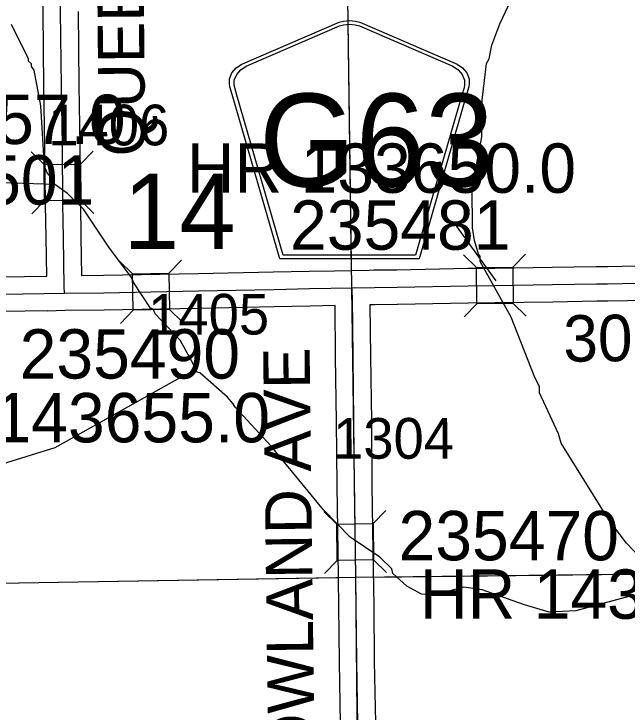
# Model space of a CAD drawing. Extents: x 23.6 to 68.7, y -63 to -29.
# Drawn here: x 49.171 to 50.226, y -54.804 to -53.602 of the extents above; entities that cross this region are included whole.
import ezdxf

# ---------------------------------------------------------------- set-up
doc = ezdxf.new("R2010")
doc.units = 0
for name, color, linetype in [('tdCoHydroRiver', 7, 'Continuous'), ('tdCoSecRdNmbr', 7, 'Continuous'), ('tdCoSecRdTxt', 7, 'Continuous'), ('tdCoSecRteBand', 7, 'Continuous'), ('tdCoSecRteCL', 7, 'Continuous'), ('tdCoSectLine', 7, 'Continuous'), ('tdCoSectLinePart', 7, 'Continuous'), ('tdCoSectNmbr', 7, 'Continuous'), ('tdCoShieldCoRte', 7, 'Continuous'), ('tdCoStrucSec', 7, 'Continuous'), ('tdCoStrucSecCoName', 7, 'Continuous'), ('tdCoStrucSecFHWANum', 7, 'Continuous'), ('tdCoSurfGravel', 7, 'Continuous')]:
    doc.layers.add(name, color=color, linetype=linetype)

msp = doc.modelspace()

# ---------------------------------------------------------------- linework, layer by layer
at = {"layer": 'tdCoHydroRiver'}
for points in [[(50.3308, -54.624), (50.3291, -54.6114), (50.2494, -54.5381), (50.2254, -54.5131), (50.195, -54.4724), (50.1131, -54.3407), (50.1082, -54.3249), (50.0758, -54.2543), (50.0757, -54.2432), (50.0676, -54.2275), (50.027, -54.1238), (49.9739, -54.0281), (49.9738, -54.0186), (49.9706, -54.0155), (49.964, -53.9919), (49.9606, -53.9698), (49.9599, -53.9019), (49.9763, -53.8133), (49.9772, -53.7502), (49.9843, -53.687), (49.989, -53.679), (49.9935, -53.6553), (50.0073, -53.6188), (50.052, -53.5236)], [(49.2416, -53.8956), (49.2367, -53.8846), (49.2287, -53.8752), (49.2238, -53.8642), (49.218, -53.7601), (49.2062, -53.6987), (49.2014, -53.6924), (49.2014, -53.6877), (49.1966, -53.683), (49.1965, -53.6782), (49.1788, -53.6437), (49.1675, -53.6201)], [(49.2416, -53.8956), (48.8404, -53.8826)], [(49.485, -54.2181), (49.4802, -54.2055), (49.4576, -54.1632), (49.4145, -54.1179), (49.4112, -54.11), (49.4065, -54.1085), (49.3776, -54.0646), (49.3727, -54.0536), (49.3359, -54.0051), (49.2909, -53.9377), (49.2638, -53.9111), (49.2416, -53.8956)], [(49.485, -54.2181), (49.4583, -54.2279), (49.2418, -54.3486), (49.1584, -54.3748), (49.1317, -54.3893), (49.1192, -54.4021), (49.1022, -54.4323), (49.0745, -54.4973), (49.0216, -54.5705), (48.9998, -54.5944), (48.97, -54.6153), (48.7404, -54.6967), (48.6604, -54.7402), (48.5626, -54.746), (48.5391, -54.7605), (48.5127, -54.8018), (48.4876, -54.821), (48.4736, -54.837), (48.4469, -54.8515), (48.4251, -54.8754), (48.367, -54.9076)], [(50.3308, -54.624), (50.2296, -54.6046), (50.1383, -54.6293), (50.0926, -54.6314), (50.0498, -54.6192), (49.9769, -54.5932), (49.9453, -54.5888), (49.8949, -54.602), (49.8728, -54.6006), (49.8474, -54.5867), (49.8235, -54.5649), (49.8218, -54.557), (49.8011, -54.5367), (49.7502, -54.5025), (49.7039, -54.4557), (49.6143, -54.3461), (49.552, -54.2789), (49.5488, -54.2727), (49.5392, -54.2617), (49.4914, -54.2196), (49.485, -54.2181)]]:
    msp.add_lwpolyline(points, dxfattribs=at)
at = {"layer": 'tdCoSecRteBand'}
for points in [[(49.1511, -54.0542), (49.2278, -54.053), (49.2268, -53.9869), (49.2257, -53.9301), (49.2257, -53.9299), (49.2257, -53.9298), (49.2248, -53.8292), (49.2231, -53.7261), (49.2231, -53.726), (49.2231, -53.7259), (49.2217, -53.5985), (49.2207, -53.5196), (49.22, -53.4565), (49.218, -53.3304), (49.218, -53.3303), (49.218, -53.3302), (49.2171, -53.2338), (49.2163, -53.2007), (49.2163, -53.2005), (49.2163, -53.2003), (49.2156, -53.1162), (49.1917, -53.1169), (49.1707, -53.1175)], [(49.2817, -53.5978), (49.2831, -53.7252), (49.2848, -53.8283), (49.2848, -53.8284), (49.2848, -53.8285), (49.2857, -53.9291), (49.2868, -53.9858), (49.2868, -53.9859), (49.2868, -53.986), (49.2878, -54.052), (49.288, -54.052), (49.288, -54.0521)], [(49.288, -54.0521), (49.3258, -54.0516), (49.4887, -54.0486), (49.6178, -54.046), (49.6796, -54.0447), (49.6797, -54.0447), (49.6797, -54.0447), (49.7228, -54.0438), (49.7528, -54.0432), (49.7828, -54.0427), (49.791, -54.0425), (49.7912, -54.0425), (49.7913, -54.0425), (49.8304, -54.0422), (49.9522, -54.0397), (49.9524, -54.0397), (49.9525, -54.0397), (49.9987, -54.0392), (50.0975, -54.0377), (50.1733, -54.0364), (50.1734, -54.0364), (50.1736, -54.0364), (50.1926, -54.0363), (50.2944, -54.0343)], [(49.7333, -54.8231), (49.7315, -54.7177), (49.7314, -54.7176), (49.7314, -54.7175), (49.7305, -54.6213), (49.7291, -54.5271), (49.7275, -54.414), (49.7275, -54.4139), (49.7275, -54.4138), (49.7265, -54.3034), (49.7249, -54.1922), (49.7249, -54.1922), (49.7249, -54.1921), (49.724, -54.1038), (49.6809, -54.1046), (49.6191, -54.106), (49.6191, -54.106), (49.6191, -54.106), (49.4898, -54.1086), (49.4898, -54.1086), (49.4898, -54.1086), (49.3268, -54.1115), (49.3268, -54.1116), (49.3267, -54.1116), (49.2591, -54.1125), (49.2294, -54.1134), (49.2294, -54.113), (49.1521, -54.1142)], [(50.2955, -54.0943), (50.1936, -54.0963), (50.1935, -54.0963), (50.1933, -54.0963), (50.1742, -54.0964), (50.0985, -54.0977), (50.0985, -54.0977), (50.0985, -54.0977), (49.9995, -54.0992), (49.9994, -54.0992), (49.9994, -54.0992), (49.9533, -54.0997), (49.8315, -54.1022), (49.8313, -54.1022), (49.8311, -54.1022), (49.792, -54.1025), (49.784, -54.1027), (49.7849, -54.1914), (49.7865, -54.3027), (49.7865, -54.3027), (49.7865, -54.3028), (49.7875, -54.4132), (49.7891, -54.5262), (49.7891, -54.5263), (49.7891, -54.5263), (49.7905, -54.6205), (49.7905, -54.6205), (49.7905, -54.6206), (49.7914, -54.7168), (49.7933, -54.8221)]]:
    msp.add_lwpolyline(points, dxfattribs=at)
at = {"layer": 'tdCoSecRteCL'}
for points in [[(49.2585, -54.0825), (49.2581, -54.0707), (49.2568, -53.9864), (49.2557, -53.9295), (49.2548, -53.8288), (49.2531, -53.7256), (49.2517, -53.5981), (49.2507, -53.5193), (49.25, -53.4561), (49.248, -53.3299), (49.2471, -53.2333), (49.2463, -53.2), (49.2456, -53.1102), (49.2453, -53.0923), (49.2451, -53.0852)], [(49.7534, -54.0732), (49.7916, -54.0725), (49.8309, -54.0722), (49.9528, -54.0697), (49.999, -54.0692), (50.098, -54.0677), (50.1738, -54.0664), (50.193, -54.0663), (50.295, -54.0643), (50.3543, -54.0635), (50.4671, -54.0608), (50.5172, -54.0602), (50.6184, -54.0585), (50.6935, -54.0567), (50.7385, -54.0561), (50.7459, -54.056)], [(49.2585, -54.0825), (49.3263, -54.0816), (49.4892, -54.0786), (49.6184, -54.076), (49.6803, -54.0746), (49.7534, -54.0732)], [(49.7657, -55.0385), (49.7659, -55.009), (49.7651, -54.9385), (49.7637, -54.8494), (49.7633, -54.8226), (49.7614, -54.7172), (49.7605, -54.6209), (49.7591, -54.5267), (49.7575, -54.4136), (49.7565, -54.3031), (49.7549, -54.1918), (49.7539, -54.0904), (49.7536, -54.0808), (49.7534, -54.0732)], [(48.7633, -54.0905), (48.7877, -54.0901), (48.9263, -54.0881), (48.9822, -54.0873), (49.1201, -54.0848), (49.1515, -54.0842), (49.2585, -54.0825)]]:
    msp.add_lwpolyline(points, dxfattribs=at)
at = {"layer": 'tdCoSectLine'}
for points in [[(49.7452, -53.5733), (49.7594, -54.5716)], [(49.7594, -54.5716), (50.7529, -54.5599)], [(48.7707, -54.5882), (49.7594, -54.5716)], [(49.7594, -54.5716), (49.7688, -55.5715)]]:
    msp.add_lwpolyline(points, dxfattribs=at)
at = {"layer": 'tdCoSectLinePart'}
for points in [[(49.7452, -53.5733), (49.7519, -54.0438)], [(49.7895, -54.5713), (50.7229, -54.5602)], [(48.8007, -54.5877), (49.7299, -54.5721)]]:
    msp.add_lwpolyline(points, dxfattribs=at)
at = {"layer": 'tdCoShieldCoRte'}
for points in [[(49.6289, -54.0233), (49.547, -53.7404), (49.5431, -53.7273), (49.5424, -53.7214), (49.5424, -53.7135), (49.5466, -53.7032), (49.5539, -53.6948), (49.5635, -53.6881), (49.7308, -53.6157), (49.7383, -53.6141), (49.7487, -53.6132), (49.7591, -53.6141), (49.7666, -53.6157), (49.9339, -53.6881), (49.9435, -53.6948), (49.9508, -53.7032), (49.955, -53.7135), (49.955, -53.7214), (49.9543, -53.7273), (49.9504, -53.7404), (49.8685, -54.0233)], [(49.6348, -54.017), (49.5551, -53.7417), (49.5513, -53.7291), (49.5506, -53.7234), (49.5506, -53.7159), (49.5547, -53.706), (49.5617, -53.6979), (49.5709, -53.6915), (49.7315, -53.622), (49.7387, -53.6204), (49.7487, -53.6196), (49.7587, -53.6204), (49.7659, -53.622), (49.9265, -53.6915), (49.9357, -53.6979), (49.9427, -53.706), (49.9468, -53.7159), (49.9468, -53.7234), (49.9461, -53.7291), (49.9423, -53.7417), (49.8626, -54.017)]]:
    msp.add_lwpolyline(points, close=True, dxfattribs=at)
at = {"layer": 'tdCoStrucSec'}
for p, q in [((49.2234, -53.8611), (49.2011, -53.8392)), ((49.286, -53.8606), (49.308, -53.8382)), ((49.2866, -53.9232), (49.3089, -53.9451)), ((49.224, -53.9237), (49.2021, -53.9461)), ((49.9674, -54.0383), (49.9451, -54.0164)), ((50.03, -54.0376), (50.0519, -54.0152)), ((49.3755, -54.0493), (49.3529, -54.0276)), ((49.4381, -54.0482), (49.4598, -54.0257)), ((49.9681, -54.1009), (49.9463, -54.1232)), ((50.0307, -54.1002), (50.0531, -54.122)), ((49.3766, -54.1119), (49.3549, -54.1345)), ((49.4392, -54.1108), (49.4617, -54.1325)), ((49.7268, -54.4801), (49.7044, -54.4583)), ((49.7894, -54.4792), (49.8112, -54.4567)), ((49.7277, -54.5427), (49.7059, -54.5651)), ((49.7903, -54.5418), (49.8128, -54.5636))]:
    msp.add_line(p, q, dxfattribs=at)
for points in [[(49.224, -53.9237), (49.2234, -53.8611), (49.286, -53.8606), (49.2866, -53.9232)], [(49.9674, -54.0383), (50.03, -54.0376), (50.0307, -54.1002), (49.9681, -54.1009)], [(49.3755, -54.0493), (49.4381, -54.0482), (49.4392, -54.1108), (49.3766, -54.1119)], [(49.7277, -54.5427), (49.7268, -54.4801), (49.7894, -54.4792), (49.7903, -54.5418)]]:
    msp.add_lwpolyline(points, close=True, dxfattribs=at)
at = {"layer": 'tdCoStrucSecFHWANum'}
msp.add_line((49.9291, -53.9622), (50.0004, -54.0614), dxfattribs=at)
at = {"layer": 'tdCoSurfGravel'}
for points in [[(49.2585, -54.0825), (49.2581, -54.0707), (49.2568, -53.9864), (49.2557, -53.9295), (49.2548, -53.8288), (49.2531, -53.7256), (49.2517, -53.5981), (49.2507, -53.5193), (49.25, -53.4561), (49.248, -53.3299), (49.2471, -53.2333), (49.2463, -53.2), (49.2456, -53.1102), (49.2453, -53.0923), (49.2451, -53.0852), (49.245, -53.078), (49.2447, -53.0604), (49.2441, -53.0086), (49.2427, -52.8982), (49.241, -52.8091), (49.2399, -52.7281), (49.239, -52.6569), (49.2383, -52.6339)], [(49.1515, -54.0842), (49.2585, -54.0825), (49.3263, -54.0816), (49.4892, -54.0786), (49.6184, -54.076), (49.6803, -54.0746), (49.7534, -54.0732), (49.7916, -54.0725), (49.8309, -54.0722), (49.9528, -54.0697), (49.999, -54.0692), (50.098, -54.0677), (50.1738, -54.0664), (50.193, -54.0663), (50.295, -54.0643), (50.3543, -54.0635), (50.4671, -54.0608), (50.5172, -54.0602), (50.6184, -54.0585), (50.6935, -54.0567), (50.7385, -54.0561), (50.7459, -54.056)], [(49.7664, -55.0693), (49.7655, -55.0632), (49.765, -55.057), (49.7648, -55.0508), (49.7651, -55.0446), (49.7657, -55.0385), (49.7659, -55.009), (49.7651, -54.9385), (49.7637, -54.8494), (49.7633, -54.8226), (49.7614, -54.7172), (49.7605, -54.6209), (49.7591, -54.5267), (49.7575, -54.4136), (49.7565, -54.3031), (49.7549, -54.1918), (49.7539, -54.0904), (49.7536, -54.0808), (49.7534, -54.0732)]]:
    msp.add_lwpolyline(points, dxfattribs=at)

# ---------------------------------------------------------------- texts
at = {"layer": 'tdCoSecRdNmbr'}
for s, rotation, p in [('1406', 0.0382, (49.2305, -53.8281)), ('1405', 0.0383, (49.4024, -54.1538)), ('1304', 0.0385, (49.7205, -54.3675))]:
    msp.add_text(s, height=0.07, rotation=rotation, dxfattribs=at).set_placement(p)
at = {"layer": 'tdCoSecRdTxt'}
for s, rotation, p in [('QUEENS AVE', 90.488, (49.3974, -53.8467)), ('305TH ST', 0.6298, (50.1172, -54.2006)), ('ROWLAND AVE', 90.7035, (49.6899, -54.9661))]:
    msp.add_text(s, height=0.08, rotation=rotation, dxfattribs=at).set_placement(p)
at = {"layer": 'tdCoSectNmbr'}
msp.add_text('14', height=0.13, rotation=0.0382, dxfattribs=at).set_placement((49.3594, -54.0067))
at = {"layer": 'tdCoShieldCoRte'}
msp.add_text('G63', height=0.16, dxfattribs=at).set_placement((49.5932, -53.899))
at = {"layer": 'tdCoStrucSecCoName'}
for s, p in [('HR 143657.0', (48.6938, -53.8257)), ('HR 133650.0', (49.4689, -53.9097)), ('HR 143655.0', (48.9422, -54.3393)), ('HR 143654.0', (49.87, -54.643))]:
    msp.add_text(s, height=0.085, dxfattribs=at).set_placement(p)
at = {"layer": 'tdCoStrucSecFHWANum'}
for s, p in [('235501', (48.9305, -53.9299)), ('235481', (49.6466, -54.0077)), ('235490', (49.1813, -54.2295)), ('235470', (49.8332, -54.5424))]:
    msp.add_text(s, height=0.085, dxfattribs=at).set_placement(p)

doc.saveas('drawing.dxf')
